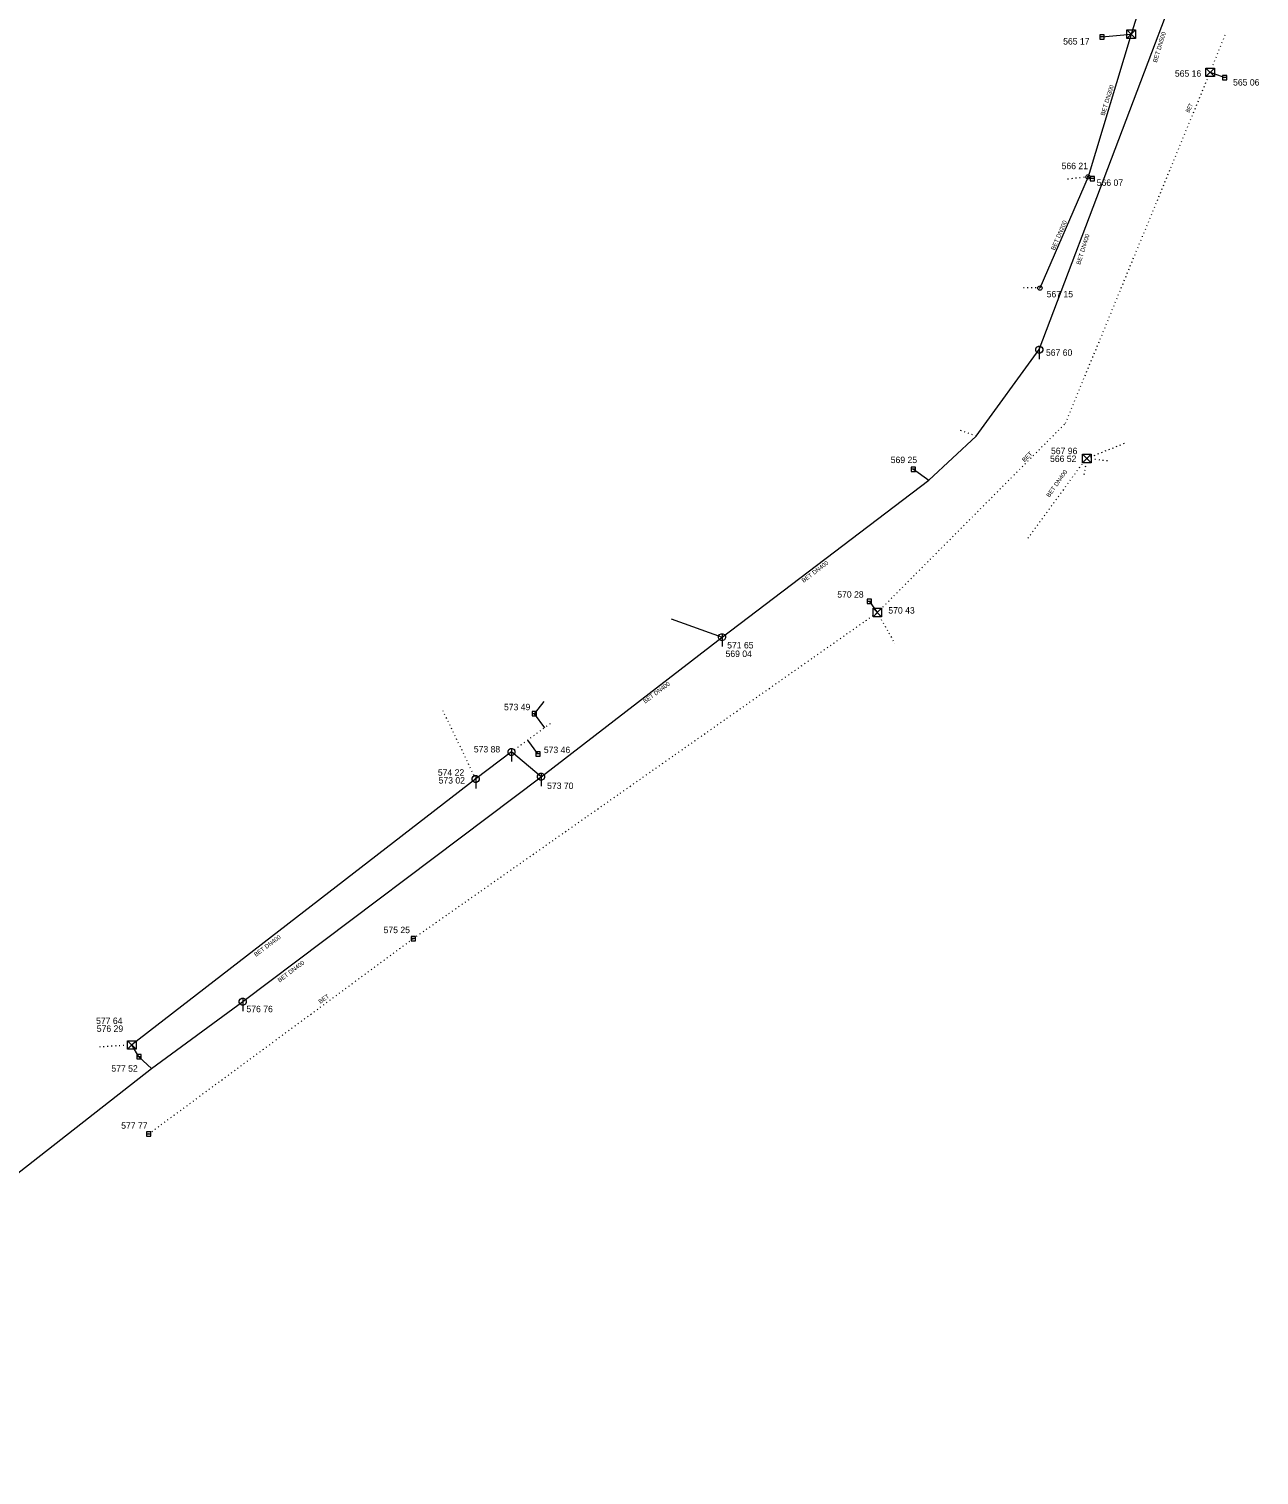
# Model space of a CAD drawing. Extents: x -710806 to -710046, y -1116920 to -1116046.
# Drawn here: x -710662.8 to -710519.6, y -1116862.7 to -1116694.3 of the extents above; entities that cross this region are included whole.
import ezdxf
from ezdxf.enums import TextEntityAlignment as Align

# ---------------------------------------------------------------- set-up
doc = ezdxf.new("R2010")
doc.units = 0
doc.header["$LTSCALE"] = 0.3
doc.linetypes.add('DOTTED', pattern=[1.5, 0.3, -1.2])
for name, color, linetype, lineweight in [('40', 7, 'Continuous', 13), ('41', 7, 'Continuous', 13), ('45', 7, 'DOTTED', 13)]:
    doc.layers.add(name, color=color, linetype=linetype, lineweight=lineweight)
doc.layers.add('43', color=7, linetype='Continuous')
doc.layers.add('44', color=7, linetype='Continuous')

msp = doc.modelspace()

# ---------------------------------------------------------------- linework, layer by layer
at = {"layer": '40', "linetype": 'DOTTED'}
for p, q in [((-710539.689, -1116744.279), (-710535.056, -1116742.398)), ((-710539.725, -1116744.202), (-710546.652, -1116753.702)), ((-710610.837, -1116781.602), (-710614.634, -1116773.691)), ((-710606.681, -1116778.465), (-710601.91, -1116774.966))]:
    msp.add_line(p, q, dxfattribs=at)
at = {"layer": '40'}
for points in [[(-710545.241, -1116731.616), (-710526.717, -1116682.642), (-710530.499, -1116682.028), (-710534.547, -1116694.887), (-710539.549, -1116711.494), (-710545.154, -1116724.439)], [(-710603.228, -1116781.343), (-710582.163, -1116765.089), (-710558.104, -1116746.801), (-710552.57, -1116741.705), (-710545.241, -1116731.616)], [(-710710.163, -1116862.665), (-710701.994, -1116856.17), (-710672.966, -1116834.362), (-710648.579, -1116815.338), (-710637.958, -1116807.538), (-710603.228, -1116781.343), (-710606.681, -1116778.465), (-710610.837, -1116781.602), (-710650.875, -1116812.584)]]:
    msp.add_lwpolyline(points, dxfattribs=at)
at = {"layer": '40', "linetype": 'DOTTED'}
msp.add_lwpolyline([(-710648.925, -1116822.954), (-710618.098, -1116800.188), (-710564.089, -1116762.23), (-710542.174, -1116740.174), (-710525.345, -1116699.321), (-710523.486, -1116694.679)], dxfattribs=at)
at = {"layer": '41'}
for p, q in [((-710537.688, -1116694.943), (-710538.188, -1116694.943)), ((-710538.188, -1116694.943), (-710538.188, -1116695.443)), ((-710537.688, -1116695.193), (-710538.188, -1116695.193)), ((-710538.188, -1116695.443), (-710537.688, -1116695.443)), ((-710537.688, -1116695.443), (-710537.688, -1116694.943)), ((-710535.047, -1116694.387), (-710534.047, -1116695.387)), ((-710534.047, -1116694.387), (-710535.047, -1116695.387)), ((-710525.845, -1116698.821), (-710524.845, -1116699.821)), ((-710524.845, -1116698.821), (-710525.845, -1116699.821)), ((-710523.391, -1116699.692), (-710523.891, -1116699.692)), ((-710523.891, -1116699.692), (-710523.891, -1116700.192)), ((-710523.391, -1116699.942), (-710523.891, -1116699.942)), ((-710523.891, -1116700.192), (-710523.391, -1116700.192)), ((-710523.391, -1116700.192), (-710523.391, -1116699.692)), ((-710538.797, -1116711.442), (-710539.297, -1116711.442)), ((-710539.297, -1116711.442), (-710539.297, -1116711.942)), ((-710538.797, -1116711.692), (-710539.297, -1116711.692)), ((-710539.297, -1116711.942), (-710538.797, -1116711.942)), ((-710538.797, -1116711.942), (-710538.797, -1116711.442)), ((-710545.241, -1116731.216), (-710545.241, -1116732.716)), ((-710540.189, -1116743.779), (-710539.189, -1116744.779)), ((-710539.189, -1116743.779), (-710540.189, -1116744.779)), ((-710559.642, -1116745.295), (-710560.142, -1116745.295)), ((-710560.142, -1116745.295), (-710560.142, -1116745.795)), ((-710559.642, -1116745.545), (-710560.142, -1116745.545)), ((-710560.142, -1116745.795), (-710559.642, -1116745.795)), ((-710559.642, -1116745.795), (-710559.642, -1116745.295)), ((-710564.755, -1116760.679), (-710565.255, -1116760.679)), ((-710565.255, -1116760.679), (-710565.255, -1116761.179)), ((-710564.755, -1116760.929), (-710565.255, -1116760.929)), ((-710565.255, -1116761.179), (-710564.755, -1116761.179)), ((-710564.755, -1116761.179), (-710564.755, -1116760.679)), ((-710564.589, -1116761.73), (-710563.589, -1116762.73)), ((-710563.589, -1116761.73), (-710564.589, -1116762.73)), ((-710582.163, -1116764.689), (-710582.163, -1116766.189)), ((-710603.782, -1116773.757), (-710604.282, -1116773.757)), ((-710604.282, -1116773.757), (-710604.282, -1116774.257)), ((-710603.782, -1116774.007), (-710604.282, -1116774.007)), ((-710604.282, -1116774.257), (-710603.782, -1116774.257)), ((-710603.782, -1116774.257), (-710603.782, -1116773.757)), ((-710606.681, -1116778.065), (-710606.681, -1116779.565)), ((-710603.352, -1116778.444), (-710603.852, -1116778.444)), ((-710603.852, -1116778.444), (-710603.852, -1116778.944)), ((-710603.352, -1116778.694), (-710603.852, -1116778.694)), ((-710603.852, -1116778.944), (-710603.352, -1116778.944)), ((-710603.352, -1116778.944), (-710603.352, -1116778.444)), ((-710610.837, -1116781.202), (-710610.837, -1116782.702)), ((-710603.228, -1116780.943), (-710603.228, -1116782.443)), ((-710617.848, -1116799.938), (-710618.348, -1116799.938)), ((-710618.348, -1116799.938), (-710618.348, -1116800.438)), ((-710617.848, -1116800.438), (-710617.848, -1116799.938)), ((-710617.848, -1116800.188), (-710618.348, -1116800.188)), ((-710618.348, -1116800.438), (-710617.848, -1116800.438)), ((-710637.958, -1116807.138), (-710637.958, -1116808.638)), ((-710651.375, -1116812.084), (-710650.375, -1116813.084)), ((-710650.375, -1116812.084), (-710651.375, -1116813.084)), ((-710649.794, -1116813.706), (-710650.294, -1116813.706)), ((-710650.294, -1116813.706), (-710650.294, -1116814.206)), ((-710649.794, -1116813.956), (-710650.294, -1116813.956)), ((-710650.294, -1116814.206), (-710649.794, -1116814.206)), ((-710649.794, -1116814.206), (-710649.794, -1116813.706)), ((-710648.675, -1116822.704), (-710649.175, -1116822.704)), ((-710649.175, -1116822.704), (-710649.175, -1116823.204)), ((-710648.675, -1116822.954), (-710649.175, -1116822.954)), ((-710649.175, -1116823.204), (-710648.675, -1116823.204)), ((-710648.675, -1116823.204), (-710648.675, -1116822.704))]:
    msp.add_line(p, q, dxfattribs=at)
for points in [[(-710535.047, -1116694.387), (-710534.047, -1116694.387), (-710534.047, -1116695.387), (-710535.047, -1116695.387)], [(-710525.845, -1116698.821), (-710524.845, -1116698.821), (-710524.845, -1116699.821), (-710525.845, -1116699.821)], [(-710545.641, -1116731.716), (-710545.641, -1116731.516), (-710545.541, -1116731.316), (-710545.341, -1116731.216), (-710545.141, -1116731.216), (-710544.941, -1116731.316), (-710544.841, -1116731.516), (-710544.841, -1116731.716), (-710544.941, -1116731.916), (-710545.141, -1116732.016), (-710545.341, -1116732.016), (-710545.541, -1116731.916)], [(-710540.189, -1116743.779), (-710539.189, -1116743.779), (-710539.189, -1116744.779), (-710540.189, -1116744.779)], [(-710564.589, -1116761.73), (-710563.589, -1116761.73), (-710563.589, -1116762.73), (-710564.589, -1116762.73)], [(-710582.563, -1116765.189), (-710582.563, -1116764.989), (-710582.463, -1116764.789), (-710582.263, -1116764.689), (-710582.063, -1116764.689), (-710581.863, -1116764.789), (-710581.763, -1116764.989), (-710581.763, -1116765.189), (-710581.863, -1116765.389), (-710582.063, -1116765.489), (-710582.263, -1116765.489), (-710582.463, -1116765.389)], [(-710607.081, -1116778.565), (-710607.081, -1116778.365), (-710606.981, -1116778.165), (-710606.781, -1116778.065), (-710606.581, -1116778.065), (-710606.381, -1116778.165), (-710606.281, -1116778.365), (-710606.281, -1116778.565), (-710606.381, -1116778.765), (-710606.581, -1116778.865), (-710606.781, -1116778.865), (-710606.981, -1116778.765)], [(-710611.237, -1116781.702), (-710611.237, -1116781.502), (-710611.137, -1116781.302), (-710610.937, -1116781.202), (-710610.737, -1116781.202), (-710610.537, -1116781.302), (-710610.437, -1116781.502), (-710610.437, -1116781.702), (-710610.537, -1116781.902), (-710610.737, -1116782.002), (-710610.937, -1116782.002), (-710611.137, -1116781.902)], [(-710603.628, -1116781.443), (-710603.628, -1116781.243), (-710603.528, -1116781.043), (-710603.328, -1116780.943), (-710603.128, -1116780.943), (-710602.928, -1116781.043), (-710602.828, -1116781.243), (-710602.828, -1116781.443), (-710602.928, -1116781.643), (-710603.128, -1116781.743), (-710603.328, -1116781.743), (-710603.528, -1116781.643)], [(-710638.358, -1116807.638), (-710638.358, -1116807.438), (-710638.258, -1116807.238), (-710638.058, -1116807.138), (-710637.858, -1116807.138), (-710637.658, -1116807.238), (-710637.558, -1116807.438), (-710637.558, -1116807.638), (-710637.658, -1116807.838), (-710637.858, -1116807.938), (-710638.058, -1116807.938), (-710638.258, -1116807.838)], [(-710651.375, -1116812.084), (-710650.375, -1116812.084), (-710650.375, -1116813.084), (-710651.375, -1116813.084)]]:
    msp.add_lwpolyline(points, close=True, dxfattribs=at)
for centre in [(-710539.549, -1116711.494), (-710545.154, -1116724.439)]:
    msp.add_circle(centre, 0.25, dxfattribs=at)
at = {"layer": '45', "linetype": 'Continuous'}
for p, q in [((-710537.938, -1116695.193), (-710534.547, -1116694.887)), ((-710525.345, -1116699.321), (-710523.641, -1116699.942)), ((-710539.549, -1116711.494), (-710539.047, -1116711.692)), ((-710559.892, -1116745.545), (-710558.104, -1116746.801)), ((-710565.005, -1116760.929), (-710564.089, -1116762.23)), ((-710588.096, -1116762.944), (-710582.163, -1116765.089)), ((-710602.909, -1116772.58), (-710604.032, -1116774.007)), ((-710604.032, -1116774.007), (-710602.832, -1116775.642)), ((-710603.602, -1116778.694), (-710604.787, -1116777.076))]:
    msp.add_line(p, q, dxfattribs=at)
at = {"layer": '45'}
for p, q in [((-710539.549, -1116711.494), (-710541.957, -1116711.763)), ((-710545.154, -1116724.439), (-710547.053, -1116724.42)), ((-710552.57, -1116741.705), (-710554.686, -1116740.926)), ((-710539.689, -1116744.279), (-710540.079, -1116746.378)), ((-710539.689, -1116744.279), (-710537.301, -1116744.526)), ((-710564.089, -1116762.23), (-710562.05, -1116765.835)), ((-710650.875, -1116812.584), (-710654.984, -1116812.841))]:
    msp.add_line(p, q, dxfattribs=at)
at = {"layer": '45', "linetype": 'Continuous'}
msp.add_lwpolyline([(-710648.579, -1116815.338), (-710650.044, -1116813.956), (-710650.875, -1116812.584)], dxfattribs=at)

# ---------------------------------------------------------------- texts
at = {"layer": '43'}
for s, p in [('565 17 ', (-710540.7812, -1116696.087)), ('565 16 ', (-710527.7782, -1116699.833)), ('565 06 ', (-710521.0002, -1116700.864)), ('566 21 ', (-710540.9612, -1116710.599)), ('566 07 ', (-710536.8732, -1116712.548)), ('567 15 ', (-710542.7002, -1116725.524)), ('567 60 ', (-710542.7862, -1116732.332)), ('569 25 ', (-710560.8522, -1116744.826)), ('567 96 ', (-710542.1972, -1116743.782)), ('570 28 ', (-710567.0782, -1116760.492)), ('570 43 ', (-710561.1302, -1116762.349)), ('571 65 ', (-710579.8922, -1116766.411)), ('573 49 ', (-710605.8762, -1116773.605)), ('573 88 ', (-710609.3872, -1116778.518)), ('573 46 ', (-710601.2342, -1116778.595)), ('574 22 ', (-710613.5732, -1116781.226)), ('573 70 ', (-710600.8562, -1116782.773)), ('575 25 ', (-710619.8892, -1116799.561)), ('576 76 ', (-710635.8542, -1116808.767)), ('577 64 ', (-710653.3572, -1116810.139)), ('577 52 ', (-710651.5782, -1116815.691)), ('577 77 ', (-710650.4362, -1116822.344))]:
    msp.add_text(s, height=0.75, dxfattribs=at).set_placement(p, align=Align.CENTER)
for s, p in [('566 52', (-710543.983, -1116744.695)), ('569 04', (-710581.756, -1116767.401)), ('573 02', (-710615.158, -1116782.139)), ('576 29', (-710654.949, -1116811.057))]:
    msp.add_text(s, height=0.75, dxfattribs=at).set_placement(p)
at = {"layer": '44'}
for s, rotation, p in [('BET DN500', 72.9, (-710531.556, -1116698.223)), ('BET DN300', 72.9, (-710537.636, -1116704.403)), ('BET DN200', 66.6, (-710543.451, -1116720.083)), ('BET DN400', 72.9, (-710540.463, -1116721.763)), ('BET', 45, (-710546.946, -1116744.738)), ('BET DN400', 54.9, (-710544.057, -1116748.852)), ('BET DN400', 36.9, (-710572.669, -1116758.773)), ('BET DN400', 36.9, (-710591.111, -1116772.838)), ('BET DN400', 36.9, (-710636.417, -1116802.331)), ('BET DN400', 36.9, (-710633.67, -1116805.319)), ('BET', 36, (-710628.927, -1116807.803))]:
    msp.add_text(s, height=0.5, rotation=rotation, dxfattribs=at).set_placement(p)
at = {"layer": '44', "width": 0.65}
msp.add_text('BET', height=0.5, rotation=63, dxfattribs=at).set_placement((-710527.787, -1116704.055))

doc.saveas('drawing.dxf')
